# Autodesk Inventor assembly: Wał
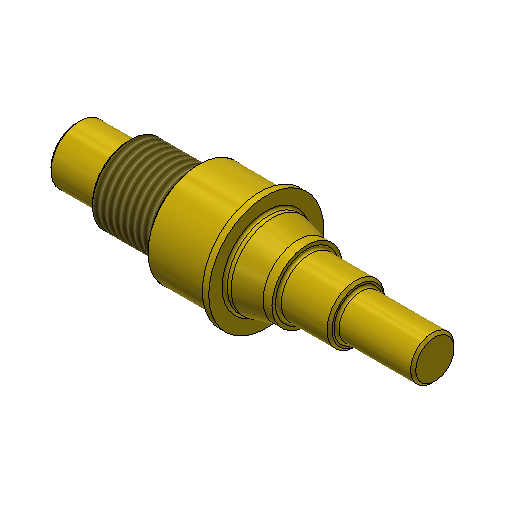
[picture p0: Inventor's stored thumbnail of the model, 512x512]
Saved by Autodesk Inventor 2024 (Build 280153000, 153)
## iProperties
ClientObjectVersion: 1
Company: ATC
Created: 2023-03
Part Number: Wał
Document SubType Name: Assembly
Designer: Andrzej Jaskulski
Checked By: A.J.
Engr Approved By: Andrzej Jaskulski
Mfg Approved By: Andrzej Jaskulski
Authority: A.J.
Title: A.J.: Kurs R2024-MEP
Author: Andrzej Jaskulski
Revision Number: 1/24
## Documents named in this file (2)
- C:\Users\AndJas\Documents\R2024-MEP\Obszar roboczy\PZ\PZ-Obliczenia wału-Dane\Design Accelerator\Wał1.iam
- C:\Users\AndJas\Documents\R2024-MEP\Obszar roboczy\PZ\PZ-Obliczenia wału-Dane\Design Accelerator\Wał1.ipt
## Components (1 placed, 1 different names)
1. Wał:1
